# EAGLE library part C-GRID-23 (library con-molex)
CONNECTOR wire to board 2.54 mm (0.100") pitch header
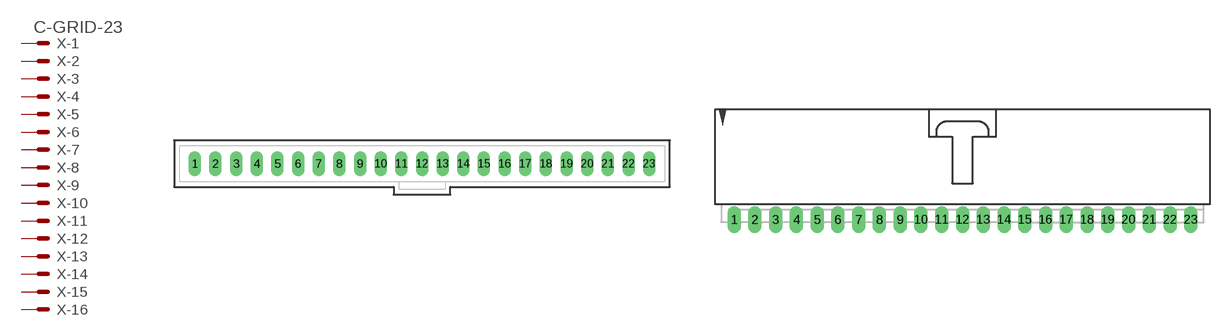
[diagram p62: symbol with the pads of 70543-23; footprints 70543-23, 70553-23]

Designator prefix X; gates -1=MV -2=M -3=M -4=M -5=M -6=M -7=M -8=M -9=M -10=M -11=M -12=M -13=M -14=M -15=M -16=M -17=M -18=M -19=M -20=M -21=M -22=M -23=M

## C-GRID-23-70543 (OC_FARNELL: unknown; OC_NEWARK: unknown)  [70543-23]
1  -1:S  pas
2  -2:S  pas
3  -3:S  pas
4  -4:S  pas
5  -5:S  pas
6  -6:S  pas
7  -7:S  pas
8  -8:S  pas
9  -9:S  pas
10  -10:S  pas
11  -11:S  pas
12  -12:S  pas
13  -13:S  pas
14  -14:S  pas
15  -15:S  pas
16  -16:S  pas
17  -17:S  pas
18  -18:S  pas
19  -19:S  pas
20  -20:S  pas
21  -21:S  pas
22  -22:S  pas
23  -23:S  pas

## C-GRID-23-70553 (OC_FARNELL: unknown; OC_NEWARK: unknown)  [70553-23]
Pads as for 70543-23

## Footprint 70543-23 (pad centres in mm)
C-Grid SL Connector vertical, 23 pin
drill 1.016 long: 1 -27.94,0; 2 -25.4,0; 3 -22.86,0; 4 -20.32,0; 5 -17.78,0; 6 -15.24,0; 7 -12.7,0; 8 -10.16,0; 9 -7.62,0; 10 -5.08,0; 11 -2.54,0; 12 0,0; 13 2.54,0; 14 5.08,0; 15 7.62,0; 16 10.16,0; 17 12.7,0; 18 15.24,0; 19 17.78,0; 20 20.32,0; 21 22.86,0; 22 25.4,0; 23 27.94,0

## Footprint 70553-23 (pad centres in mm)
C-Grid SL Connector right angle, 23 pin
drill 1.092 long: 1 -27.94,-7.62; 2 -25.4,-7.62; 3 -22.86,-7.62; 4 -20.32,-7.62; 5 -17.78,-7.62; 6 -15.24,-7.62; 7 -12.7,-7.62; 8 -10.16,-7.62; 9 -7.62,-7.62; 10 -5.08,-7.62; 11 -2.54,-7.62; 12 0,-7.62; 13 2.54,-7.62; 14 5.08,-7.62; 15 7.62,-7.62; 16 10.16,-7.62; 17 12.7,-7.62; 18 15.24,-7.62; 19 17.78,-7.62; 20 20.32,-7.62; 21 22.86,-7.62; 22 25.4,-7.62; 23 27.94,-7.62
